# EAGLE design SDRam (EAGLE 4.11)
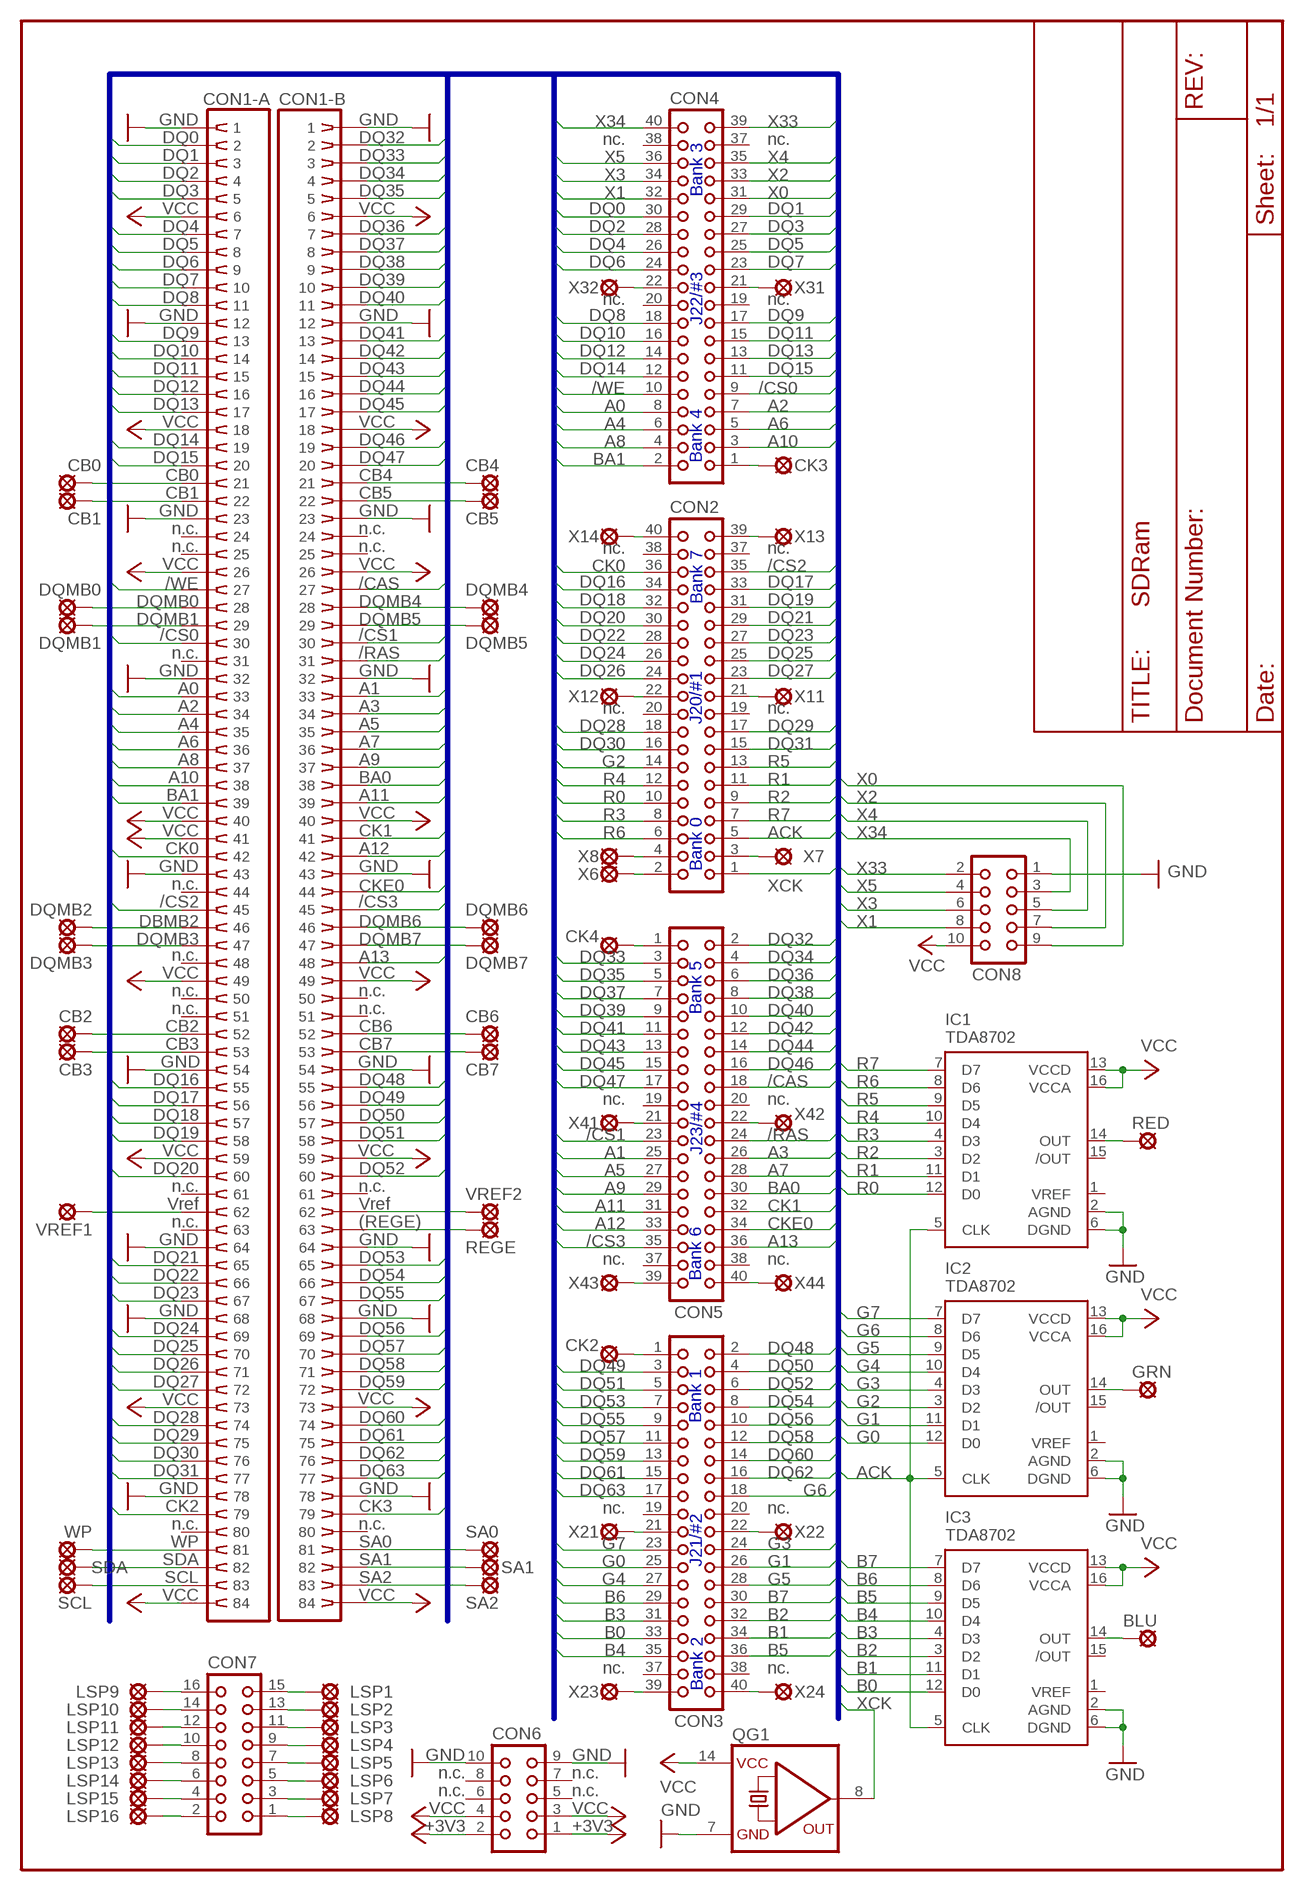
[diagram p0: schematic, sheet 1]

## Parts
BLU  LSP10  [LSP10]
CB0  LSP10  [LSP10]
CB1  LSP10  [LSP10]
CB2  LSP10  [LSP10]
CB3  LSP10  [LSP10]
CB4  LSP10  [LSP10]
CB5  LSP10  [LSP10]
CB6  LSP10  [LSP10]
CB7  LSP10  [LSP10]
CK2  LSP10  [LSP10]
CK3  LSP10  [LSP10]
CK4  LSP10  [LSP10]
CON1  DIMM84  [382830-1]
CON2  CON40  [CON40]
CON3  CON40  [CON40]
CON4  CON40  [CON40]
CON5  CON40  [CON40]
CON6  CON10  [CON10]
CON7  CON16  [CON16]
CON8  CON10  [CON10]
DQMB0  LSP10  [LSP10]
DQMB1  LSP10  [LSP10]
DQMB2  LSP10  [LSP10]
DQMB3  LSP10  [LSP10]
DQMB4  LSP10  [LSP10]
DQMB5  LSP10  [LSP10]
DQMB6  LSP10  [LSP10]
DQMB7  LSP10  [LSP10]
GRN  LSP10  [LSP10]
IC1  TDA8702  [SO16W]
IC2  TDA8702  [SO16W]
IC3  TDA8702  [SO16W]
LSP1  LSP10  [LSP10]
LSP2  LSP10  [LSP10]
LSP3  LSP10  [LSP10]
LSP4  LSP10  [LSP10]
LSP5  LSP10  [LSP10]
LSP6  LSP10  [LSP10]
LSP7  LSP10  [LSP10]
LSP8  LSP10  [LSP10]
LSP9  LSP10  [LSP10]
LSP10  LSP10  [LSP10]
LSP11  LSP10  [LSP10]
LSP12  LSP10  [LSP10]
LSP13  LSP10  [LSP10]
LSP14  LSP10  [LSP10]
LSP15  LSP10  [LSP10]
LSP16  LSP10  [LSP10]
QG1  QG5860  [DIL14S]
RED  LSP10  [LSP10]
REGE  LSP10  [LSP10]
SA0  LSP10  [LSP10]
SA1  LSP10  [LSP10]
SA2  LSP10  [LSP10]
SCL  LSP10  [LSP10]
SDA  LSP10  [LSP10]
VREF1  LSP10  [LSP10]
VREF2  LSP10  [LSP10]
WP  LSP10  [LSP10]
X6  LSP10  [LSP10]
X7  LSP10  [LSP10]
X8  LSP10  [LSP10]
X11  LSP10  [LSP10]
X12  LSP10  [LSP10]
X13  LSP10  [LSP10]
X14  LSP10  [LSP10]
X21  LSP10  [LSP10]
X22  LSP10  [LSP10]
X23  LSP10  [LSP10]
X24  LSP10  [LSP10]
X31  LSP10  [LSP10]
X32  LSP10  [LSP10]
X41  LSP10  [LSP10]
X42  LSP10  [LSP10]
X43  LSP10  [LSP10]
X44  LSP10  [LSP10]

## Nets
+3V3: CON6.1 CON6.2
/CAS: CON1.111 CON5.18
/CS0: CON1.30 CON4.9
/CS1: CON1.114 CON5.23
/CS2: CON1.45 CON2.35
/CS3: CON1.129 CON5.35
/RAS: CON1.115 CON5.24
/WE: CON1.27 CON4.10
A0: CON1.33 CON4.8
A1: CON1.117 CON5.25
A2: CON1.34 CON4.7
A3: CON1.118 CON5.26
A4: CON1.35 CON4.6
A5: CON1.119 CON5.27
A6: CON1.36 CON4.5
A7: CON1.120 CON5.28
A8: CON1.37 CON4.4
A9: CON1.121 CON5.29
A10: CON1.38 CON4.3
A11: CON1.123 CON5.31
A12: CON1.126 CON5.33
A13: CON1.132 CON5.36
ACK: CON2.5 IC1.5(CLK) IC2.5(CLK) IC3.5(CLK)
B0: CON3.33 IC3.12(D0)
B1: CON3.34 IC3.11(D1)
B2: CON3.32 IC3.3(D2)
B3: CON3.31 IC3.4(D3)
B4: CON3.35 IC3.10(D4)
B5: CON3.36 IC3.9(D5)
B6: CON3.29 IC3.8(D6)
B7: CON3.30 IC3.7(D7)
BA0: CON1.122 CON5.30
BA1: CON1.39 CON4.2
CK0: CON1.42 CON2.36
CK1: CON1.125 CON5.32
CK2: CON1.79
CK3: CON1.163
CKE0: CON1.128 CON5.34
DBMB2: CON1.46 DQMB2.MP
DQ0: CON1.2 CON4.30
DQ1: CON1.3 CON4.29
DQ2: CON1.4 CON4.28
DQ3: CON1.5 CON4.27
DQ4: CON1.7 CON4.26
DQ5: CON1.8 CON4.25
DQ6: CON1.9 CON4.24
DQ7: CON1.10 CON4.23
DQ8: CON1.11 CON4.18
DQ9: CON1.13 CON4.17
DQ10: CON1.14 CON4.16
DQ11: CON1.15 CON4.15
DQ12: CON1.16 CON4.14
DQ13: CON1.17 CON4.13
DQ14: CON1.19 CON4.12
DQ15: CON1.20 CON4.11
DQ16: CON1.55 CON2.34
DQ17: CON1.56 CON2.33
DQ18: CON1.57 CON2.32
DQ19: CON1.58 CON2.31
DQ20: CON1.60 CON2.30
DQ21: CON1.65 CON2.29
DQ22: CON1.66 CON2.28
DQ23: CON1.67 CON2.27
DQ24: CON1.69 CON2.26
DQ25: CON1.70 CON2.25
DQ26: CON1.71 CON2.24
DQ27: CON1.72 CON2.23
DQ28: CON1.74 CON2.18
DQ29: CON1.75 CON2.17
DQ30: CON1.76 CON2.16
DQ31: CON1.77 CON2.15
DQ32: CON1.86 CON5.2
DQ33: CON1.87 CON5.3
DQ34: CON1.88 CON5.4
DQ35: CON1.89 CON5.5
DQ36: CON1.91 CON5.6
DQ37: CON1.92 CON5.7
DQ38: CON1.93 CON5.8
DQ39: CON1.94 CON5.9
DQ40: CON1.95 CON5.10
DQ41: CON1.97 CON5.11
DQ42: CON1.98 CON5.12
DQ43: CON1.99 CON5.13
DQ44: CON1.100 CON5.14
DQ45: CON1.101 CON5.15
DQ46: CON1.103 CON5.16
DQ47: CON1.104 CON5.17
DQ48: CON1.139 CON3.2
DQ49: CON1.140 CON3.3
DQ50: CON1.141 CON3.4
DQ51: CON1.142 CON3.5
DQ52: CON1.144 CON3.6
DQ53: CON1.149 CON3.7
DQ54: CON1.150 CON3.8
DQ55: CON1.151 CON3.9
DQ56: CON1.153 CON3.10
DQ57: CON1.154 CON3.11
DQ58: CON1.155 CON3.12
DQ59: CON1.156 CON3.13
DQ60: CON1.158 CON3.14
DQ61: CON1.159 CON3.15
DQ62: CON1.160 CON3.16
DQ63: CON1.161 CON3.17
DQMB0: CON1.28 DQMB0.MP
DQMB1: CON1.29 DQMB1.MP
DQMB3: CON1.47 DQMB3.MP
DQMB4: CON1.112 DQMB4.MP
DQMB5: CON1.113 DQMB5.MP
DQMB6: CON1.130 DQMB6.MP
DQMB7: CON1.131 DQMB7.MP
G0: CON3.25 IC2.12(D0)
G1: CON3.26 IC2.11(D1)
G2: CON2.14 IC2.3(D2)
G3: CON3.24 IC2.4(D3)
G4: CON3.27 IC2.10(D4)
G5: CON3.28 IC2.9(D5)
G6: CON3.18 IC2.8(D6)
G7: CON3.23 IC2.7(D7)
GND: CON1.1 CON1.12 CON1.23 CON1.32 CON1.43 CON1.54 CON1.64 CON1.68 CON1.78 CON1.85 CON1.96 CON1.107 CON1.116 CON1.127 CON1.138 CON1.148 CON1.152 CON1.162 CON6.9 CON6.10 CON8.1 IC1.2(AGND) IC1.6(DGND) IC2.2(AGND) IC2.6(DGND) IC3.2(AGND) IC3.6(DGND) QG1.7(GND)
N$1: CB0.MP CON1.21
N$2: CB1.MP CON1.22
N$3: CB4.MP CON1.105
N$4: CB5.MP CON1.106
N$5: CB2.MP CON1.52
N$6: CB3.MP CON1.53
N$7: CON1.62 VREF1.MP
N$8: CON1.146 VREF2.MP
N$9: CON1.81 WP.MP
N$10: CON1.82 SDA.MP
N$11: CB6.MP CON1.136
N$12: CB7.MP CON1.137
N$13: CON1.83 SCL.MP
N$14: CON1.167 SA2.MP
N$15: CON1.165 SA0.MP
N$16: CON1.166 SA1.MP
N$17: CON1.147 REGE.MP
N$20: CON4.22 X32.MP
N$21: CON4.21 X31.MP
N$22: CK3.MP CON4.1
N$23: CON2.40 X14.MP
N$24: CON2.39 X13.MP
N$25: CON2.21 X11.MP
N$27: CON2.22 X12.MP
N$28: IC1.14(OUT) RED.MP
N$29: CON5.40 X44.MP
N$30: CON5.22 X42.MP
N$31: CON5.21 X41.MP
N$32: CON5.39 X43.MP
N$33: CK4.MP CON5.1
N$34: CK2.MP CON3.1
N$35: CON3.22 X22.MP
N$36: CON3.40 X24.MP
N$37: CON3.39 X23.MP
N$38: CON3.21 X21.MP
N$39: CON2.4 X8.MP
N$40: CON2.2 X6.MP
N$41: CON2.3 X7.MP
N$42: GRN.MP IC2.14(OUT)
N$43: CON7.16 LSP9.MP
N$44: CON7.14 LSP10.MP
N$45: CON7.12 LSP11.MP
N$46: CON7.10 LSP12.MP
N$47: CON7.8 LSP13.MP
N$48: CON7.6 LSP14.MP
N$49: CON7.4 LSP15.MP
N$50: CON7.2 LSP16.MP
N$51: CON7.15 LSP1.MP
N$52: CON7.13 LSP2.MP
N$53: CON7.11 LSP3.MP
N$54: CON7.9 LSP4.MP
N$55: CON7.7 LSP5.MP
N$56: CON7.5 LSP6.MP
N$57: CON7.3 LSP7.MP
N$58: CON7.1 LSP8.MP
N$59: BLU.MP IC3.14(OUT)
R0: CON2.10 IC1.12(D0)
R1: CON2.11 IC1.11(D1)
R2: CON2.9 IC1.3(D2)
R3: CON2.8 IC1.4(D3)
R4: CON2.12 IC1.10(D4)
R5: CON2.13 IC1.9(D5)
R6: CON2.6 IC1.8(D6)
R7: CON2.7 IC1.7(D7)
VCC: CON1.6 CON1.18 CON1.26 CON1.40 CON1.41 CON1.49 CON1.59 CON1.73 CON1.84 CON1.90 CON1.102 CON1.110 CON1.124 CON1.133 CON1.143 CON1.157 CON1.168 CON6.3 CON6.4 CON8.10 IC1.13(VCCD) IC1.16(VCCA) IC2.13(VCCD) IC2.16(VCCA) IC3.13(VCCD) IC3.16(VCCA) QG1.14(VCC)
X0: CON4.31 CON8.9
X1: CON4.32 CON8.8
X2: CON4.33 CON8.7
X3: CON4.34 CON8.6
X4: CON4.35 CON8.5
X5: CON4.36 CON8.4
X33: CON4.39 CON8.2
X34: CON4.40 CON8.3
XCK: CON2.1 QG1.8(OUT)
Unconnected: CON1.24 CON1.25 CON1.31 CON1.44 CON1.48 CON1.50 CON1.51 CON1.61 CON1.63 CON1.80 CON1.108 CON1.109 CON1.134 CON1.135 CON1.145 CON1.164 CON2.19 CON2.20 CON2.37 CON2.38 CON3.19 CON3.20 CON3.37 CON3.38 CON4.19 CON4.20 CON4.37 CON4.38 CON5.19 CON5.20 CON5.37 CON5.38 CON6.5 CON6.6 CON6.7 CON6.8 IC1.1(VREF) IC1.15(/OUT) IC2.1(VREF) IC2.15(/OUT) IC3.1(VREF) IC3.15(/OUT)

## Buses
ADBUS:DQ[0..63],A[0..13],/RAS,/CAS,/WE,/CS[0..3],BA[0..1],CK[0..3],CKE0,R[0..7],G[0..7],B[0..7],X[0..5],XCK,ACK,X33,X34

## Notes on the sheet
- nc. | nc.
- Bank 3
- nc. | nc.
- J22/#3
- Bank 4
- CB0 | CB4
- CB1 | CB5
- n.c. | n.c.
- n.c. | n.c. | nc. | nc.
- Bank 7
- n.c.
- nc. | nc.
- J20/#1
- BA0
- BA1
- CK1
- CK0
- Bank 0
- n.c.
- n.c.
- n.c. | n.c.
- n.c. | n.c. | Bank 5
- CB2 | CB6
- CB3 | CB7
- nc. | nc.
- J23/#4
- n.c. | n.c.
- Vref | Vref
- n.c. | (REGE)
- nc. | nc.
- Bank 6
- Bank 1
- CK2 | CK3 | nc. | nc.
- n.c. | n.c.
- WP | SA0
- SDA | SA1 | J21/#2
- SCL | SA2
- nc. | nc.
- Bank 2
- n.c. | n.c.
- n.c. | n.c.

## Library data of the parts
BLU CB0 CB1-CB7 CK2-CK4 DQMB0 DQMB1-DQMB7 GRN LSP1-LSP16 RED REGE SA0 SA1 SA2 SCL SDA VREF1 VREF2 WP X6-X8 X11-X14 X21-X24 X31 X32 X41-X44 = SDRam1:LSP10: SOLDER PAD
CON1 = SDRam1:DIMM84: AMP connector
CON2-CON5 = SDRam1:CON40: CONNECTOR
CON6 CON8 = SDRam1:CON10: CONNECTOR
CON7 = SDRam1:CON16: CONNECTOR
IC1-IC3 = SDRam1:TDA8702: Video-DAC Philips
QG1 = SDRam1:QG5860: CRYSTAL RESONATOR

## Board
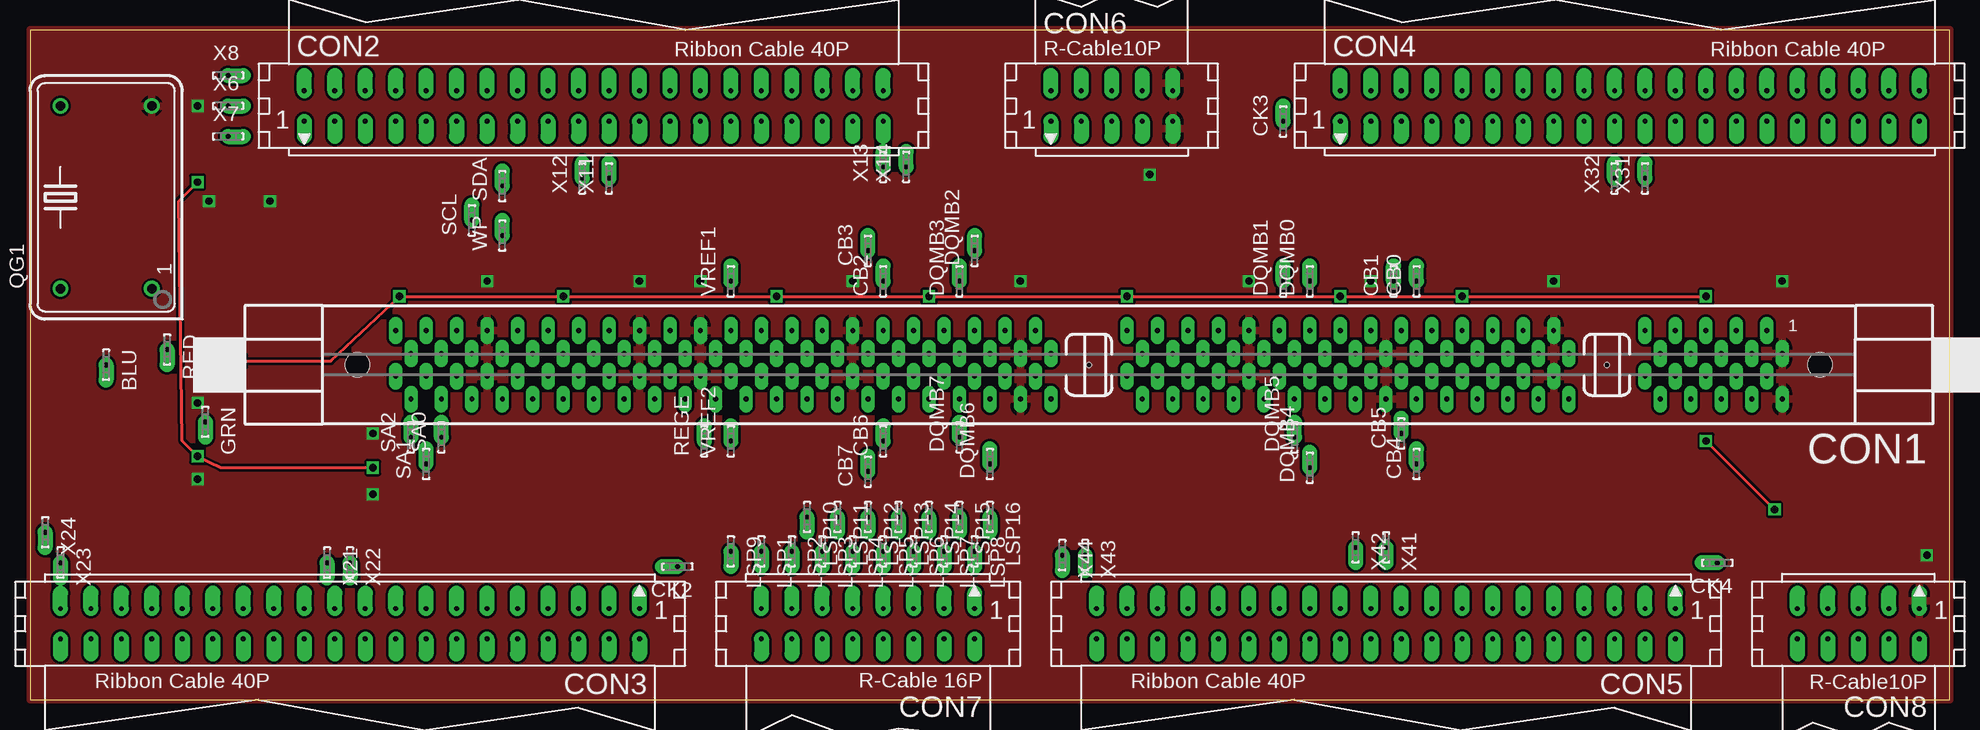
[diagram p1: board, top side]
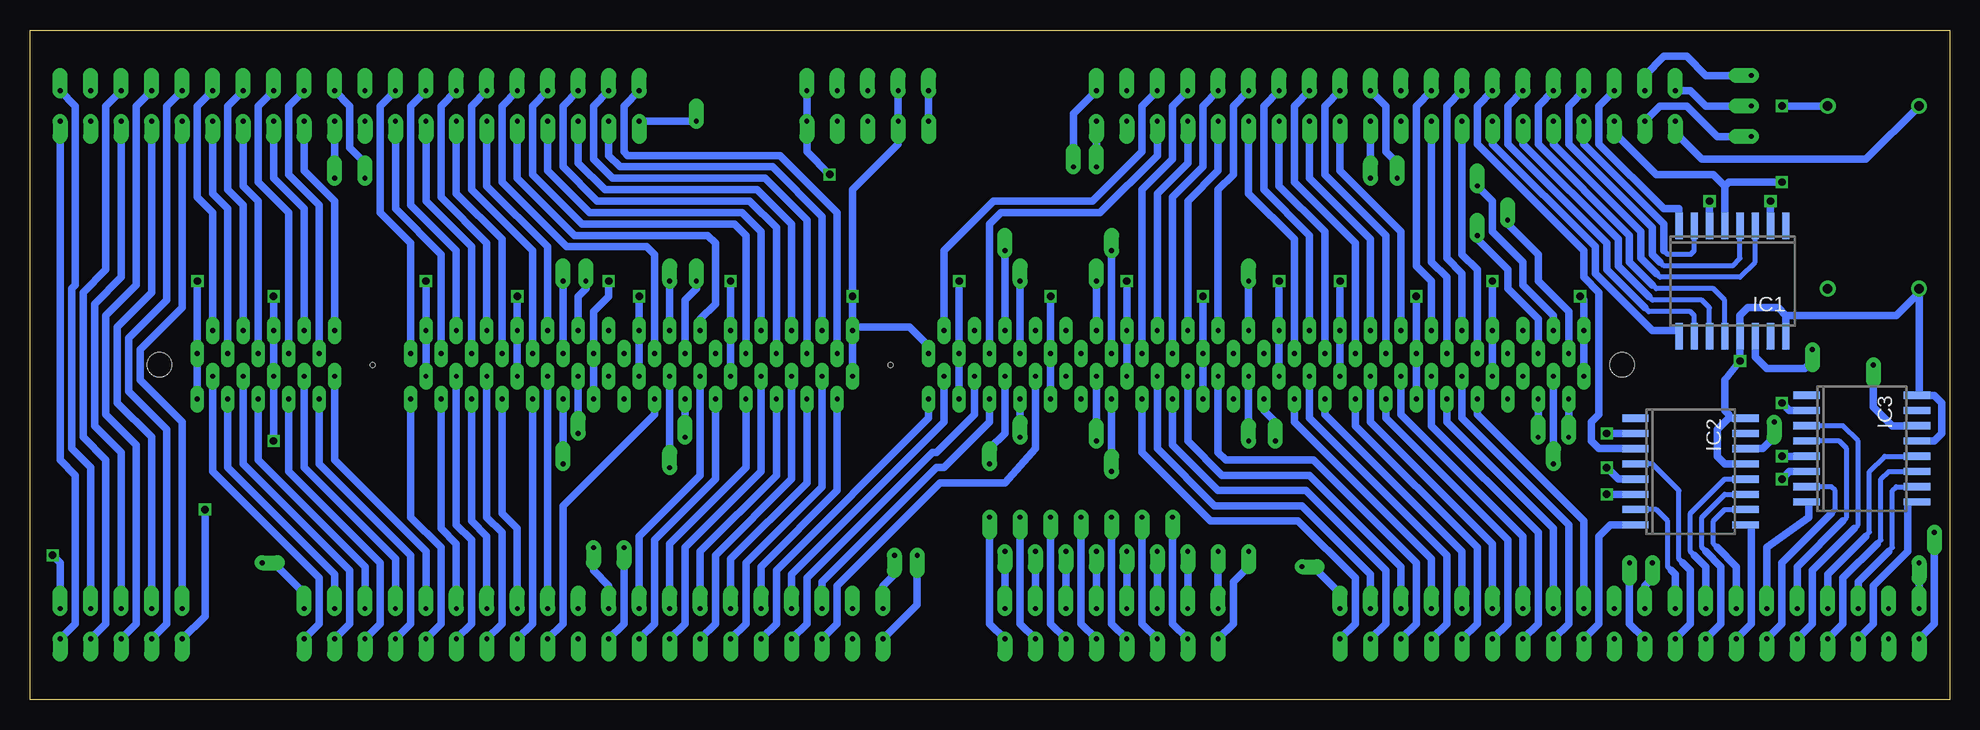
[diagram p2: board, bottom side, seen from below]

Size 160 x 55.87 mm. Coordinates in mm from the lower left corner, seen from the top.
Outline: 0,0 160,0 160,55.87 0,55.87 0,0
Copper layers (1*16): Top 0.035mm / dielectric 1.5mm / Bottom 0.035mm
Design rules "default": minimum track width 10mil, minimum drill 24mil, track to track 8mil, track to pad 8mil, pad to pad 8mil, via to via 8mil, smd to smd 8mil, copper to edge 0mil, drill to drill 8mil, minimum pad ring 10mil, minimum via ring 8mil, stop-mask expansion 4mil, vias tented up to drill 0mil, thermal gap 10mil

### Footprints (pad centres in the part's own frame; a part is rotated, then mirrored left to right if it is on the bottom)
LSP10 = drill 0.406 pad 1.27 offset: MP 0,0
382830-1 = drill 0.406 pad 1.143 long: 1 -57.785,-0.953; 2 -56.515,-2.857; 3 -55.245,-0.953; 4 -53.975,-2.857; 5 -52.705,-0.953; 6 -51.435,-2.857; 7 -50.165,-0.953; 8 -48.895,-2.857; 9 -47.625,-0.953; 10 -46.355,-2.857; 11 -40.005,-0.953; 12 -38.735,-2.857; 13 -37.465,-0.953; 14 -36.195,-2.857; 15 -34.925,-0.953; 16 -33.655,-2.857; 17 -32.385,-0.953; 18 -31.115,-2.857; 19 -29.845,-0.953; 20 -28.575,-2.857; 21 -27.305,-0.953; 22 -26.035,-2.857; 23 -24.765,-0.953; 24 -23.495,-2.857; 25 -22.225,-0.953; 26 -20.955,-2.857; 27 -19.685,-0.953; 28 -18.415,-2.857; 29 -17.145,-0.953; 30 -15.875,-2.857; 31 -14.605,-0.953; 32 -13.335,-2.857; 33 -12.065,-0.953; 34 -10.795,-2.857; 35 -9.525,-0.953; 36 -8.255,-2.857; 37 -6.985,-0.953; 38 -5.715,-2.857; 39 -4.445,-0.953; 40 -3.175,-2.857; 41 3.175,-0.953; 42 4.445,-2.857; 43 5.715,-0.953; 44 6.985,-2.857; 45 8.255,-0.953; 46 9.525,-2.857; 47 10.795,-0.953; 48 12.065,-2.857; 49 13.335,-0.953; 50 14.605,-2.857; 51 15.875,-0.953; 52 17.145,-2.857; 53 18.415,-0.953; 54 19.685,-2.857; 55 20.955,-0.953; 56 22.225,-2.857; 57 23.495,-0.953; 58 24.765,-2.857; 59 26.035,-0.953; 60 27.305,-2.857; 61 28.575,-0.953; 62 29.845,-2.857; 63 31.115,-0.953; 64 32.385,-2.857; 65 33.655,-0.953; 66 34.925,-2.857; 67 36.195,-0.953; 68 37.465,-2.857; 69 38.735,-0.953; 70 40.005,-2.857; 71 41.275,-0.953; 72 42.545,-2.857; 73 43.815,-0.953; 74 45.085,-2.857; 75 46.355,-0.953; 76 47.625,-2.857; 77 48.895,-0.953; 78 50.165,-2.857; 79 51.435,-0.953; 80 52.705,-2.857; 81 53.975,-0.953; 82 55.245,-2.857; 83 56.515,-0.953; 84 57.785,-2.857; 85 -57.785,2.857; 86 -56.515,0.953; 87 -55.245,2.857; 88 -53.975,0.953; 89 -52.705,2.857; 90 -51.435,0.953; 91 -50.165,2.857; 92 -48.895,0.953; 93 -47.625,2.857; 94 -46.355,0.953; 95 -40.005,2.857; 96 -38.735,0.953; 97 -37.465,2.857; 98 -36.195,0.953; 99 -34.925,2.857; 100 -33.655,0.953; 101 -32.385,2.857; 102 -31.115,0.953; 103 -29.845,2.857; 104 -28.575,0.953; 105 -27.305,2.857; 106 -26.035,0.953; 107 -24.765,2.857; 108 -23.495,0.953; 109 -22.225,2.857; 110 -20.955,0.953; 111 -19.685,2.857; 112 -18.415,0.953; 113 -17.145,2.857; 114 -15.875,0.953; 115 -14.605,2.857; 116 -13.335,0.953; 117 -12.065,2.857; 118 -10.795,0.953; 119 -9.525,2.857; 120 -8.255,0.953; 121 -6.985,2.857; 122 -5.715,0.953; 123 -4.445,2.857; 124 -3.175,0.953; 125 3.175,2.857; 126 4.445,0.953; 127 5.715,2.857; 128 6.985,0.953; 129 8.255,2.857; 130 9.525,0.953; 131 10.795,2.857; 132 12.065,0.953; 133 13.335,2.857; 134 14.605,0.953; 135 15.875,2.857; 136 17.145,0.953; 137 18.415,2.857; 138 19.685,0.953; 139 20.955,2.857; 140 22.225,0.953; 141 23.495,2.857; 142 24.765,0.953; 143 26.035,2.857; 144 27.305,0.953; 145 28.575,2.857; 146 29.845,0.953; 147 31.115,2.857; 148 32.385,0.953; 149 33.655,2.857; 150 34.925,0.953; 151 36.195,2.857; 152 37.465,0.953; 153 38.735,2.857; 154 40.005,0.953; 155 41.275,2.857; 156 42.545,0.953; 157 43.815,2.857; 158 45.085,0.953; 159 46.355,2.857; 160 47.625,0.953; 161 48.895,2.857; 162 50.165,0.953; 163 51.435,2.857; 164 52.705,0.953; 165 53.975,2.857; 166 55.245,0.953; 167 56.515,2.857; 168 57.785,0.953 | hole 2.032: -60.96,0; 60.96,0 | hole 0.406: 0,0; -43.18,0
CON40 = drill 0.406 pad 1.27 offset: 1 -24.13,-1.27; 2 -24.13,1.27; 3 -21.59,-1.27; 4 -21.59,1.27; 5 -19.05,-1.27; 6 -19.05,1.27; 7 -16.51,-1.27; 8 -16.51,1.27; 9 -13.97,-1.27; 10 -13.97,1.27; 11 -11.43,-1.27; 12 -11.43,1.27; 13 -8.89,-1.27; 14 -8.89,1.27; 15 -6.35,-1.27; 16 -6.35,1.27; 17 -3.81,-1.27; 18 -3.81,1.27; 19 -1.27,-1.27; 20 -1.27,1.27; 21 1.27,-1.27; 22 1.27,1.27; 23 3.81,-1.27; 24 3.81,1.27; 25 6.35,-1.27; 26 6.35,1.27; 27 8.89,-1.27; 28 8.89,1.27; 29 11.43,-1.27; 30 11.43,1.27; 31 13.97,-1.27; 32 13.97,1.27; 33 16.51,-1.27; 34 16.51,1.27; 35 19.05,-1.27; 36 19.05,1.27; 37 21.59,-1.27; 38 21.59,1.27; 39 24.13,-1.27; 40 24.13,1.27
CON10 = drill 0.406 pad 1.27 offset: 1 -5.08,-1.27; 2 -5.08,1.27; 3 -2.54,-1.27; 4 -2.54,1.27; 5 0,-1.27; 6 0,1.27; 7 2.54,-1.27; 8 2.54,1.27; 9 5.08,-1.27; 10 5.08,1.27
CON16 = drill 0.406 pad 1.27 offset: 1 -8.89,-1.27; 2 -8.89,1.27; 3 -6.35,-1.27; 4 -6.35,1.27; 5 -3.81,-1.27; 6 -3.81,1.27; 7 -1.27,-1.27; 8 -1.27,1.27; 9 1.27,-1.27; 10 1.27,1.27; 11 3.81,-1.27; 12 3.81,1.27; 13 6.35,-1.27; 14 6.35,1.27; 15 8.89,-1.27; 16 8.89,1.27
SO16W = smd 0.6 x 2.2: 1 -4.445,-4.6; 2 -3.175,-4.6; 3 -1.905,-4.6; 4 -0.635,-4.6; 5 0.635,-4.6; 6 1.905,-4.6; 7 3.175,-4.6; 8 4.445,-4.6; 9 4.445,4.6; 10 3.175,4.6; 11 1.905,4.6; 12 0.635,4.6; 13 -0.635,4.6; 14 -1.905,4.6; 15 -3.175,4.6; 16 -4.445,4.6
DIL14S = drill 0.813 round: 1 -7.62,-3.81; 7 7.62,-3.81; 8 7.62,3.81; 14 -7.62,3.81

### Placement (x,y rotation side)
BLU  6.35,27.94 270 top
CB0  115.57,34.93 90 top
CB1  113.66,34.93 90 top
CB2  71.12,34.93 90 top
CB3  69.85,37.47 90 top
CB4  115.57,19.69 90 top
CB5  114.3,22.23 90 top
CB6  71.12,21.59 90 top
CB7  69.85,19.05 90 top
CK2  53.97,11.11 180 top
CK3  104.46,48.26 90 top
CK4  140.65,11.43 180 top
CON1  88.26,27.94 180 top
CON2  46.99,49.53 0 top
CON3  26.67,6.35 180 top
CON4  133.35,49.53 0 top
CON5  113.03,6.35 180 top
CON6  90.17,49.53 0 top
CON7  69.85,6.35 180 top
CON8  152.4,6.35 180 top
DQMB0  106.68,34.93 90 top
DQMB1  104.46,34.93 90 top
DQMB2  78.74,37.47 90 top
DQMB3  77.47,34.93 90 top
DQMB4  106.68,19.37 90 top
DQMB5  105.41,21.91 90 top
DQMB6  80.01,19.69 90 top
DQMB7  77.47,21.91 90 top
GRN  14.6,23.18 270 top
IC1  18.1,34.93 180 bottom
IC2  21.59,19.05 270 bottom
IC3  7.3,20.96 270 bottom
LSP1  60.96,12.38 270 top
LSP2  63.5,12.38 270 top
LSP3  66.04,12.38 270 top
LSP4  68.58,12.38 270 top
LSP5  71.12,12.38 270 top
LSP6  73.66,12.38 270 top
LSP7  76.2,12.38 270 top
LSP8  78.74,12.38 270 top
LSP9  58.42,12.38 270 top
LSP10  64.77,15.24 270 top
LSP11  67.31,15.24 270 top
LSP12  69.85,15.24 270 top
LSP13  72.39,15.24 270 top
LSP14  74.93,15.24 270 top
LSP15  77.47,15.24 270 top
LSP16  80.01,15.24 270 top
QG1  6.35,41.91 90 top
RED  11.43,29.21 270 top
REGE  56.2,21.59 90 top
SA0  34.29,21.91 90 top
SA1  33.02,19.69 90 top
SA2  31.75,21.91 90 top
SCL  36.83,40.01 90 top
SDA  39.37,42.86 90 top
VREF1  58.42,34.93 90 top
VREF2  58.42,21.59 90 top
WP  39.37,38.74 90 top
X6  16.51,49.53 0 top
X7  16.51,46.99 0 top
X8  16.51,52.07 0 top
X11  48.26,43.5 90 top
X12  46.04,43.5 90 top
X13  71.12,44.45 90 top
X14  73.02,44.45 90 top
X21  24.76,11.43 270 top
X22  26.67,11.43 270 top
X23  2.54,11.43 270 top
X24  1.27,13.97 270 top
X31  134.62,43.5 90 top
X32  132.08,43.5 90 top
X41  113.03,12.7 270 top
X42  110.49,12.7 270 top
X43  87.95,12.07 270 top
X44  86.04,12.07 270 top

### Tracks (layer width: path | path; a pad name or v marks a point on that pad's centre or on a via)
+3V3
  Bottom 0.61: CON6.1 CON6.2
/CAS
  Bottom 0.61: CON5.18 115.57,6.35 115.57,16.19 107.95,23.81 CON1.111
/CS0
  Bottom 0.61: CON4.9 119.38,43.5 114.62,38.74 103.5,38.74 102.87,38.1 102.87,33.02 104.14,31.75 CON1.30
/CS1
  Bottom 0.61: CON1.114 104.14,18.74 109.22,13.65 CON5.23
/CS2
  Bottom 0.61: CON2.35 66.04,45.41 70.8,40.64 79.06,40.64 80.01,39.69 CON1.45
/CS3
  Bottom 0.61: CON5.35 93.98,9.84 84.45,19.37 83.82,19.37 80.01,23.18 CON1.129
/RAS
  Bottom 0.61: CON5.24 107.95,6.35 107.95,13.34 102.87,18.42 CON1.115
/WE
  Bottom 0.61: CON4.10 120.65,49.53 120.65,43.18 115.25,37.78 108.58,37.78 107.95,37.15 CON1.27
A0
  Bottom 0.61: CON4.8 118.11,49.53 118.11,43.82 113.98,39.69 101.28,39.69 100.33,38.74 CON1.33
A1
  Bottom 0.61: CON1.117 100.33,19.37 106.68,13.02 CON5.25
A2
  Bottom 0.61: CON4.7 116.84,44.14 113.35,40.64 100.65,40.64 99.06,39.06 CON1.34
A3
  Bottom 0.61: CON5.26 105.41,6.35 105.41,12.7 99.06,19.05 CON1.118
A4
  Bottom 0.61: CON4.6 115.57,49.53 115.57,44.45 112.71,41.6 100.01,41.6 97.79,39.37 CON1.35
A5
  Bottom 0.61: CON5.27 104.14,12.39 97.79,18.74 CON1.119
A6
  Bottom 0.61: CON4.5 114.3,44.77 112.08,42.55 99.38,42.55 96.52,39.69 CON1.36
A7
  Bottom 0.61: CON5.28 102.87,6.35 102.87,12.07 96.52,18.42 CON1.120
A8
  Bottom 0.61: CON4.4 113.03,49.53 113.03,45.09 111.44,43.5 98.74,43.5 95.25,40.01 CON1.37
A9
  Bottom 0.61: CON5.29 101.6,11.75 95.25,18.1 CON1.121
A10
  Bottom 0.61: CON4.3 111.76,45.41 110.81,44.45 98.11,44.45 93.98,40.32 CON1.38
A11
  Bottom 0.61: CON5.31 99.06,11.12 92.71,17.46 CON1.123
A12
  Bottom 0.61: CON5.33 96.52,10.48 83.82,23.18 CON1.126
A13
  Bottom 0.61: CON5.36 92.71,6.35 92.71,9.53 84.14,18.1 78.74,18.1 76.2,20.96 CON1.132
ACK  (via drill 0.61)
  Top 0.254: v13.97,43.18 12.38,41.6 12.7,21.59 v13.97,20.32 15.87,19.37 v28.57,19.37
  Bottom 0.61: CON2.5 27.94,47.31 24.45,43.82 19.68,43.82 18.73,42.86 | 18.73,39.37 IC1.5 18.73,42.86 | IC3.5 v13.97,20.32 | v13.97,43.18 18.41,43.18 18.73,42.86 | IC2.5 27.62,18.42 v28.57,19.37
B0
  Bottom 0.406: IC3.12 5.4,20.32 6.67,19.05 6.67,13.97 6.98,13.65
  Bottom 0.61: CON3.33 10.16,10.48 6.98,13.65
B1
  Bottom 0.406: IC3.11 5.08,19.05 5.71,18.42 5.71,13.34 6.03,13.02
  Bottom 0.61: CON3.34 8.89,6.35 8.89,10.16 6.03,13.02
B2
  Bottom 0.406: IC3.3 8.89,22.86 7.62,21.59 7.62,14.61 7.94,14.29
  Bottom 0.61: CON3.32 11.43,6.35 11.43,10.8 7.94,14.29
B3
  Bottom 0.406: IC3.4 9.21,21.59 8.57,20.96 8.57,15.24 8.89,14.92
  Bottom 0.61: CON3.31 12.7,11.12 8.89,14.92
B4
  Bottom 0.406: IC3.10 4.44,17.78 4.76,17.46 4.76,12.7 5.08,12.39
  Bottom 0.61: CON3.35 7.62,9.84 5.08,12.39
B5
  Bottom 0.61: CON3.36 6.35,6.35 6.35,9.53 3.49,12.39 3.49,16.51 IC3.9
B6
  Bottom 0.61: CON3.29 15.24,12.7 11.75,15.24 11.75,16.51 IC3.8
B7
  Bottom 0.406: IC3.7 9.84,17.78 9.52,17.46 9.52,15.88 9.84,15.56
  Bottom 0.61: CON3.30 13.97,6.35 13.97,11.43 9.84,15.56
BA0
  Bottom 0.61: CON5.30 100.33,6.35 100.33,11.43 93.98,17.78 CON1.122
BA1
  Bottom 0.61: CON4.2 110.49,49.53 110.49,45.72 110.17,45.41 97.47,45.41 92.71,40.64 CON1.39
CK0
  Bottom 0.61: CON2.36 67.31,49.53 67.31,45.72 71.44,41.6 79.69,41.6 83.82,37.47 CON1.42
CK1
  Bottom 0.61: CON5.32 97.79,6.35 97.79,10.8 85.09,23.5 CON1.125
CKE0
  Bottom 0.61: CON5.34 95.25,6.35 95.25,10.16 84.77,20.64 84.45,20.64 81.28,23.81 CON1.128
DBMB2
  Bottom 0.61: CON1.46 DQMB2.MP
DQ0
  Bottom 0.61: CON4.30 146.05,49.53 146.05,41.91 144.78,40.64 CON1.2
DQ1
  Bottom 0.61: CON1.3 143.51,40.96 144.78,42.23 CON4.29
DQ2
  Bottom 0.61: CON4.28 143.51,49.53 143.51,42.55 142.24,41.28 CON1.4
DQ3
  Bottom 0.61: CON1.5 140.97,41.6 142.24,42.86 CON4.27
DQ4
  Bottom 0.61: CON4.26 140.97,49.53 140.97,43.18 138.43,40.64 CON1.7
DQ5
  Bottom 0.61: CON1.8 137.16,40.96 139.7,43.5 CON4.25
DQ6
  Bottom 0.61: CON4.24 138.43,49.53 138.43,43.82 135.89,41.28 CON1.9
DQ7
  Bottom 0.61: CON1.10 134.62,41.6 137.16,44.14 CON4.23
DQ8
  Bottom 0.61: CON4.18 130.81,49.53 130.81,40.64 128.27,38.1 CON1.11
DQ9
  Bottom 0.61: CON1.13 125.73,37.15 129.54,40.96 CON4.17
DQ10
  Bottom 0.61: CON4.16 128.27,49.53 128.27,41.28 124.46,37.47 CON1.14
DQ11
  Bottom 0.61: CON1.15 123.19,37.78 127,41.6 CON4.15
DQ12
  Bottom 0.61: CON4.14 125.73,49.53 125.73,41.91 121.92,38.1 CON1.16
DQ13
  Bottom 0.61: CON1.17 120.65,38.42 124.46,42.23 CON4.13
DQ14
  Bottom 0.61: CON4.12 123.19,49.53 123.19,42.55 118.11,37.47 CON1.19
DQ15
  Bottom 0.61: CON4.11 121.92,42.86 116.84,37.78 CON1.20
DQ16
  Bottom 0.61: CON2.34 64.77,49.53 64.77,45.09 67.31,42.55 CON1.55
DQ17
  Bottom 0.61: CON2.33 63.5,44.77 66.04,42.23 CON1.56
DQ18
  Bottom 0.61: CON2.32 62.23,49.53 62.23,44.45 64.77,41.91 CON1.57
DQ19
  Bottom 0.61: CON1.58 63.5,41.6 60.96,44.14 CON2.31
DQ20
  Bottom 0.61: CON2.30 59.69,49.53 59.69,43.82 60.96,42.55 CON1.60
DQ21
  Bottom 0.61: CON1.65 54.61,38.42 58.42,42.23 CON2.29
DQ22
  Bottom 0.61: CON2.28 57.15,49.53 57.15,42.55 53.34,38.74 CON1.66
DQ23
  Bottom 0.61: CON1.67 52.07,39.06 55.88,42.86 CON2.27
DQ24
  Bottom 0.61: CON2.26 54.61,49.53 54.61,43.18 49.53,38.1 CON1.69
DQ25
  Bottom 0.61: 48.26,30.48 CON1.70 48.26,38.42 53.34,43.5 CON2.25
DQ26
  Bottom 0.61: CON2.24 52.07,49.53 52.07,43.82 46.99,38.74 CON1.71
DQ27
  Bottom 0.61: CON2.23 50.8,44.14 45.72,39.06 CON1.72
DQ28
  Bottom 0.61: CON2.18 44.45,49.53 44.45,36.2 43.18,34.93 CON1.74
DQ29
  Bottom 0.61: CON1.75 41.91,35.24 43.18,36.52 CON2.17
DQ30
  Bottom 0.61: CON2.16 41.91,49.53 41.91,36.83 40.64,35.56 CON1.76
DQ31
  Bottom 0.61: CON2.15 40.64,37.15 39.37,35.88 CON1.77
DQ32
  Bottom 0.61: 144.78,27.31 CON1.86 144.78,19.05 135.89,10.16 135.89,6.35 CON5.2
DQ33
  Bottom 0.61: CON5.3 134.62,10.48 143.51,19.37 CON1.87
DQ34
  Bottom 0.61: CON5.4 133.35,6.35 133.35,10.8 142.24,19.69 CON1.88
DQ35
  Bottom 0.61: 140.97,25.4 CON1.89 140.97,20.01 132.08,11.12 CON5.5
DQ36
  Bottom 0.61: CON5.6 130.81,6.35 130.81,11.43 138.43,19.05 CON1.91
DQ37
  Bottom 0.61: CON1.92 137.16,19.37 129.54,11.75 CON5.7
DQ38
  Bottom 0.61: CON5.8 128.27,6.35 128.27,12.07 135.89,19.69 CON1.93
DQ39
  Bottom 0.61: CON1.94 134.62,20.01 127,12.39 CON5.9
DQ40
  Bottom 0.61: CON5.10 125.73,6.35 125.73,12.7 128.27,15.24 CON1.95
DQ41
  Bottom 0.61: CON1.97 125.73,14.29 124.46,13.02 CON5.11
DQ42
  Bottom 0.61: CON5.12 123.19,6.35 123.19,13.34 124.46,14.61 CON1.98
DQ43
  Bottom 0.61: CON1.99 123.19,14.92 121.92,13.65 CON5.13
DQ44
  Bottom 0.61: CON5.14 120.65,6.35 120.65,13.97 121.92,15.24 CON1.100
DQ45
  Bottom 0.61: CON1.101 120.65,15.56 119.38,14.29 CON5.15
DQ46
  Bottom 0.61: CON5.16 118.11,6.35 CON1.103
DQ47
  Bottom 0.61: CON5.17 CON1.104
DQ48
  Bottom 0.61: CON3.2 49.53,6.35 49.53,10.16 54.29,14.92 61.59,14.92 67.31,20.64 CON1.139
DQ49
  Bottom 0.61: CON3.3 48.26,10.48 53.97,16.19 61.28,16.19 66.04,20.96 CON1.140
DQ50
  Bottom 0.61: CON3.4 46.99,6.35 46.99,10.8 53.66,17.46 60.96,17.46 64.77,21.28 CON1.141
DQ51
  Bottom 0.61: CON3.5 45.72,11.12 53.34,18.74 60.64,18.74 63.5,21.59 CON1.142
DQ52
  Bottom 0.61: CON3.6 44.45,6.35 44.45,11.43 53.02,20.01 60.32,20.01 60.96,20.64 CON1.144
DQ53
  Bottom 0.61: CON3.7 43.18,11.75 54.61,23.18 CON1.149
DQ54
  Bottom 0.61: CON3.8 41.91,6.35 41.91,12.07 53.34,23.5 CON1.150
DQ55
  Bottom 0.61: CON3.9 40.64,12.39 52.07,23.81 CON1.151
DQ56
  Bottom 0.61: CON3.10 39.37,6.35 39.37,12.7 49.53,22.86 CON1.153
DQ57
  Bottom 0.61: CON3.11 38.1,13.02 48.26,23.18 CON1.154
DQ58
  Bottom 0.61: CON3.12 36.83,6.35 36.83,13.34 46.99,23.5 CON1.155
DQ59
  Bottom 0.61: CON1.156 45.72,23.81 35.56,13.65 CON3.13
DQ60
  Bottom 0.61: CON3.14 34.29,6.35 34.29,13.97 43.18,22.86 CON1.158
DQ61
  Bottom 0.61: CON3.15 33.02,14.29 41.91,23.18 CON1.159
DQ62
  Bottom 0.61: CON3.16 31.75,6.35 31.75,14.61 40.64,23.5 CON1.160
DQ63
  Bottom 0.61: CON1.161 39.37,23.81 30.48,14.92 CON3.17
DQMB0
  Bottom 0.61: 106.68,30.48 CON1.28 DQMB0.MP
DQMB1
  Bottom 0.61: CON1.29 105.41,33.34 104.46,34.29 DQMB1.MP
DQMB3
  Bottom 0.61: CON1.47 DQMB3.MP
DQMB4
  Bottom 0.61: DQMB4.MP CON1.112
DQMB5
  Bottom 0.61: DQMB5.MP CON1.113
DQMB6
  Bottom 0.61: DQMB6.MP 80.01,20.96 78.74,22.23 CON1.130
DQMB7
  Bottom 0.61: DQMB7.MP CON1.131
G0
  Bottom 0.406: IC2.12 18.73,18.42 21.59,15.56 21.59,12.39 21.27,12.07
  Bottom 0.61: CON3.25 20.32,11.12 21.27,12.07
G1
  Bottom 0.406: IC2.11 18.73,17.15 20.64,15.24 20.64,12.7 20.32,12.39
  Bottom 0.61: CON3.26 19.05,6.35 19.05,11.12 20.32,12.39
G2
  Bottom 0.61: CON2.14 39.37,49.53 39.37,46.36 30.48,37.47 30.48,35.24 29.21,33.97 29.21,23.81 29.84,23.18 29.84,21.59 29.21,20.96 IC2.3
G3
  Bottom 0.406: IC2.4 24.76,19.69 22.54,17.46 22.54,11.75 22.22,11.43
  Bottom 0.61: CON3.24 21.59,6.35 21.59,10.8 22.22,11.43
G4
  Bottom 0.406: IC2.10 18.73,15.88 19.68,14.92 19.68,13.02 19.37,12.7
  Bottom 0.61: CON3.27 17.78,11.12 19.37,12.7
G5
  Bottom 0.61: CON3.28 16.51,6.35 16.51,14.61 IC2.9
G6
  Bottom 0.61: CON3.18 29.21,6.35 29.21,13.65 28.26,14.61 IC2.8
G7
  Bottom 0.406: IC2.7 24.45,15.88 23.49,14.92 23.49,11.12 23.18,10.8
  Bottom 0.61: CON3.23 22.86,10.48 23.18,10.8
GND  (via drill 0.61)
  Bottom 0.61: CON1.162 CON1.78 v38.1,34.93 | CON1.152 CON1.68 v50.8,34.93 | CON1.148 CON1.64 v55.88,34.93 | CON1.138 CON1.54 v68.58,34.93 | CON1.127 CON1.43 v82.55,34.93 | CON1.107 CON1.23 113.03,32.39 111.76,33.66 v111.76,34.93 | CON1.96 CON1.12 v127,34.93 | CON1.85 CON1.1 v146.05,34.93 | CON1.116 CON1.32 v101.6,34.93 | IC2.6 v28.57,17.15 | IC2.2 v28.57,22.23 | IC3.6 13.33,19.05 v13.97,18.42 | IC3.2 13.33,24.13 v13.97,24.77 | IC1.2 v14.92,41.6 | IC1.6 v20,41.6 | QG1.7 v13.97,49.53 | CON8.1 157.48,11.43 v158.11,12.07 | CON6.10 CON6.9 95.25,45.72 v93.34,43.82
  pour Top: 0,55.88 160.02,55.88 160.02,0 0,0
N$1
  Bottom 0.61: CON1.21 CB0.MP
N$2
  Bottom 0.61: CON1.22 114.3,33.66 113.66,34.29 CB1.MP
N$3
  Bottom 0.61: CB4.MP CON1.105
N$4
  Bottom 0.61: CB5.MP CON1.106
N$5
  Bottom 0.61: CON1.52 CB2.MP
N$6
  Bottom 0.61: CON1.53 CB3.MP
N$7
  Bottom 0.61: CON1.62 VREF1.MP
N$8
  Bottom 0.61: VREF2.MP CON1.146
N$9
  Bottom 0.61: CON1.81 34.29,31.75 36.83,34.29 36.83,35.88 39.37,38.42 WP.MP
N$10
  Bottom 0.61: CON1.82 33.02,32.07 35.56,34.61 35.56,36.52 38.1,39.06 38.1,41.6 SDA.MP
N$11
  Bottom 0.61: CB6.MP CON1.136
N$12
  Bottom 0.61: CB7.MP CON1.137
N$13
  Bottom 0.61: CON1.83 31.75,32.39 34.29,34.93 34.29,37.15 36.83,39.69 SCL.MP
N$14
  Bottom 0.61: SA2.MP CON1.167
N$15
  Bottom 0.61: SA0.MP CON1.165
N$16
  Bottom 0.61: SA1.MP CON1.166
N$17
  Bottom 0.61: REGE.MP 56.2,23.18 57.15,24.13 CON1.147
N$20
  Bottom 0.61: CON4.22 133.35,49.53 133.35,46.04 132.08,44.77 X32.MP
N$21
  Bottom 0.61: X31.MP CON4.21
N$22
  Bottom 0.61: CK3.MP CON4.1
N$23
  Bottom 0.61: CON2.40 73.02,48.9 X14.MP
N$24
  Bottom 0.61: X13.MP CON2.39
N$25
  Bottom 0.61: X11.MP CON2.21
N$27
  Bottom 0.61: CON2.22 46.99,49.53 46.99,45.72 46.04,44.77 X12.MP
N$28
  Bottom 0.61: IC1.14 16.19,28.58 15.24,27.62 12.06,27.62 11.43,28.26 RED.MP
N$29
  Bottom 0.61: CON5.40 86.04,7.94 X44.MP 86.04,12.39
N$30
  Bottom 0.61: CON5.22 110.49,6.35 X42.MP 110.49,13.02
N$31
  Bottom 0.61: CON5.21 111.76,9.53 113.03,10.8 X41.MP
N$32
  Bottom 0.61: CON5.39 88.9,9.53 87.95,10.48 X43.MP
N$33
  Bottom 0.61: CK4.MP 139.7,11.43 137.16,8.89 CON5.1
N$34
  Bottom 0.61: CON3.1 50.8,8.89 53.02,11.12 CK2.MP
N$35
  Bottom 0.61: CON3.22 26.67,6.35 X22.MP
N$36
  Bottom 0.61: CON3.40 1.27,6.35 X24.MP
N$37
  Bottom 0.61: CON3.39 X23.MP
N$38
  Bottom 0.61: CON3.21 25.4,9.53 24.76,10.16 X21.MP
N$39
  Bottom 0.61: X8.MP 20.32,52.07 21.91,53.66 23.81,53.66 25.4,52.07 CON2.4
N$40
  Bottom 0.61: X6.MP 20.32,49.53 21.59,50.8 CON2.2
N$41
  Bottom 0.61: CON2.3 24.13,49.53 21.91,49.53 19.37,46.99 X7.MP
N$42
  Bottom 0.61: IC2.14 15.56,20.96 14.6,21.91 GRN.MP
N$43
  Bottom 0.61: CON7.16 59.69,6.35 59.69,9.84 58.42,11.12 LSP9.MP
N$44
  Bottom 0.61: CON7.14 64.77,6.35 LSP10.MP
N$45
  Bottom 0.61: CON7.12 67.31,6.35 LSP11.MP
N$46
  Bottom 0.61: CON7.10 69.85,6.35 LSP12.MP
N$47
  Bottom 0.61: CON7.8 72.39,6.35 LSP13.MP
N$48
  Bottom 0.61: CON7.6 74.93,6.35 LSP14.MP
N$49
  Bottom 0.61: CON7.4 77.47,6.35 LSP15.MP
N$50
  Bottom 0.61: CON7.2 80.01,6.35 LSP16.MP
N$51
  Bottom 0.61: CON7.15 LSP1.MP
N$52
  Bottom 0.61: CON7.13 LSP2.MP
N$53
  Bottom 0.61: CON7.11 LSP3.MP
N$54
  Bottom 0.61: CON7.9 LSP4.MP
N$55
  Bottom 0.61: CON7.7 LSP5.MP
N$56
  Bottom 0.61: CON7.5 LSP6.MP
N$57
  Bottom 0.61: CON7.3 LSP7.MP
N$58
  Bottom 0.61: CON7.1 LSP8.MP
N$59
  Bottom 0.61: IC3.14 4.76,22.86 6.35,24.45 BLU.MP
R0
  Bottom 0.406: IC1.12 18.73,33.34 19.68,34.29 24.45,34.29 24.76,34.61
  Bottom 0.61: CON2.10 34.29,49.53 34.29,46.36 26.67,38.74 26.67,36.52 24.76,34.61
R1
  Bottom 0.406: IC1.11 20,32.71 20.64,33.34 24.76,33.34 25.08,33.66
  Bottom 0.61: CON2.11 35.56,46.36 27.62,38.42 27.62,36.2 25.08,33.66
R2
  Bottom 0.406: IC1.3 16.19,36.52 17.46,35.24 24.13,35.24 24.45,35.56
  Bottom 0.61: CON2.9 33.02,46.36 25.72,39.06 25.72,36.83 24.45,35.56
R3
  Bottom 0.406: IC1.4 17.46,36.83 18.1,36.2 23.81,36.2 24.13,36.52
  Bottom 0.61: CON2.8 31.75,49.53 31.75,46.36 24.76,39.37 24.76,37.15 24.13,36.52
R4
  Bottom 0.406: IC1.10 21.27,32.07 21.59,32.39 25.08,32.39 25.4,32.71
  Bottom 0.61: CON2.12 36.83,49.53 36.83,46.36 28.57,38.1 28.57,35.88 25.4,32.71
R5
  Bottom 0.406: IC1.9 22.54,30.8
  Bottom 0.61: CON2.13 38.1,46.36 29.53,37.78 29.53,35.56 24.76,30.8 22.54,30.8
R6
  Bottom 0.61: CON2.6 29.21,49.53 29.21,46.36 23.81,40.96 22.54,40.96 IC1.8
R7
  Bottom 0.406: IC1.7 21.27,37.47 21.59,37.15 23.49,37.15 23.81,37.47
  Bottom 0.61: CON2.7 30.48,46.36 23.81,39.69 23.81,37.47
VCC  (via drill 0.61)
  Top 0.254: v139.7,33.66 v119.38,33.66 v109.22,33.66 v91.44,33.66 v74.93,33.66 v62.23,33.66 v44.45,33.66 v30.8,33.66 25.08,28.26 v17.46,28.26 | v139.7,21.59 v145.41,15.88
  Bottom 0.61: CON1.157 CON1.73 v44.45,33.66 | CON1.143 CON1.59 v62.23,33.66 | CON1.133 CON1.49 v74.93,33.66 | CON1.40 CON1.124 | CON1.110 CON1.26 v109.22,33.66 | CON1.102 CON1.18 v119.38,33.66 | CON1.168 CON1.84 30.48,33.34 v30.8,33.66 | CON1.40 v91.44,33.66 91.44,42.55 87.63,46.36 CON6.3 CON6.4 | v139.7,33.66 CON1.6 CON1.90 v139.7,21.59 | CON1.41 85.09,29.53 86.68,31.12 91.12,31.12 CON1.40 | 18.41,23.5 IC2.16 | 18.41,23.5 19.37,22.55 19.37,20.32 18.73,19.69 IC2.13 | 13.65,32.07 14.29,32.71 16.83,32.71 17.46,32.07 IC1.13 v17.46,28.26 18.73,26.67 18.73,24.13 18.41,23.81 18.41,23.5 | 13.65,32.07 IC1.16 | 2.54,25.4 2.54,33.97 | IC3.13 1.27,21.59 0.63,22.23 0.63,24.77 1.27,25.4 2.54,25.4 | 2.54,25.4 IC3.16 | 2.54,33.97 QG1.14 | 2.54,33.97 4.44,32.07 13.65,32.07 | v145.41,15.88 145.41,6.99 CON8.10
X0
  Bottom 0.61: CON4.31 147.32,32.71 150.81,29.21 150.81,26.67 147.32,23.18 CON8.9
X1
  Bottom 0.61: CON4.32 148.59,49.53 148.59,33.34 151.76,30.17 151.76,25.72 148.59,22.55 148.59,6.35 CON8.8
X2
  Bottom 0.61: CON4.33 149.86,33.97 152.72,31.12 152.72,24.77 149.86,21.91 CON8.7
X3
  Bottom 0.61: CON4.34 151.13,49.53 151.13,34.61 153.67,32.07 153.67,23.81 151.13,21.28 151.13,6.35 CON8.6
X4
  Bottom 0.61: CON4.35 152.4,35.24 154.62,33.02 154.62,22.86 152.4,20.64 CON8.5
X5
  Bottom 0.61: CON4.36 153.67,49.53 153.67,35.88 155.57,33.97 155.57,21.91 153.67,20.01 153.67,6.35 CON8.4
X33
  Bottom 0.61: CON4.39 157.48,20.01 156.21,18.74 156.21,6.35 CON8.2
X34
  Bottom 0.61: CON4.40 156.21,49.53 156.21,34.61 156.53,34.29 156.53,20.96 154.94,19.37 CON8.3
XCK
  Bottom 0.61: CON2.1 22.86,47.31 20.64,45.09 6.98,45.09 QG1.8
